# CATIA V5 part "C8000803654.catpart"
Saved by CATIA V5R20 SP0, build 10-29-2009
Part number: C8000803654
Source: Unknown
Property "A": "50"
Property "ARTICLENO": "C8000803654"
Property "B": "23"
Property "BOMINFO": "C8000803654"
Property "C": "95"
Property "CA": "C8000803654"
Property "D1": "85"
Property "DES": "ROTATING EYEBOLT WITH RING Ton 8 M36x54"
Property "E": "95"
Property "H": "205"
Property "L": "54"
Property "LINA": "C8000803654"
Property "NB": "C8000803654"
Property "NBSYN": "$CODE."
Property "NN": "C800"
Property "NT": "Rotating eyebolt with ring"
Property "SIZE": "M36"
Property "SUPPLIER": "CF"
Property "SW": "75"
Property "WEIGHT": "5500"
Property "WLL": "8.00"
Bounding box of the stored display mesh (mm): x -47.825 to 48, y -54 to 227.825, z -42.5 to 42.5
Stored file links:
  C:\Users\Utente\Desktop\3D files 800\C8000803654.catpart
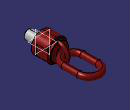
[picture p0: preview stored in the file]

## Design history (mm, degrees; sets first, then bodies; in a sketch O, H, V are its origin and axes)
Body1 "Geometry.1" (main body)
  Solid1 "C8000803654.catpart": solid without history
